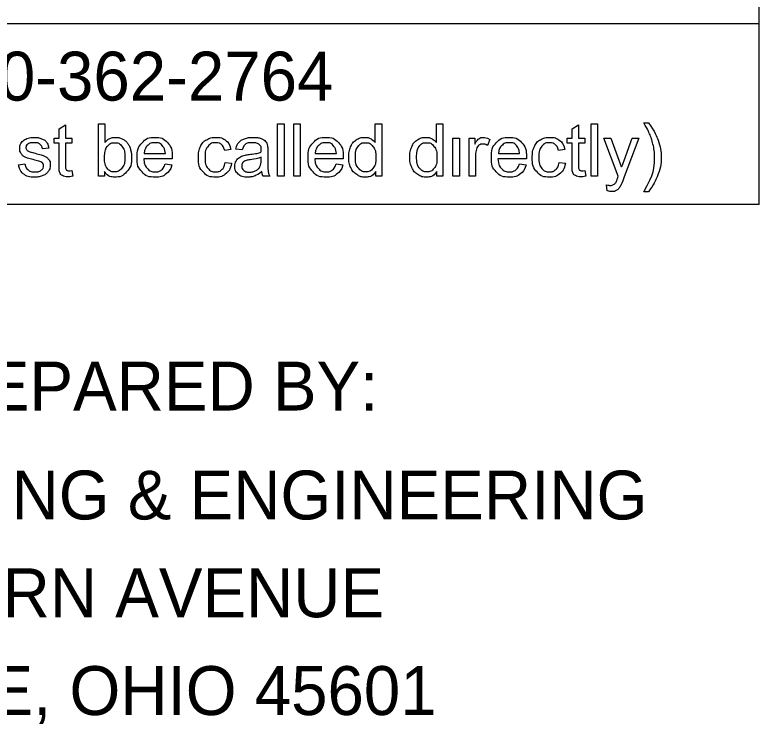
# Model space of a CAD drawing. Extents: x 0 to 82.7, y -0.2 to 22.
# Drawn here: x 55.657 to 57.787, y -0.049 to 1.983 of the extents above; entities that cross this region are included whole.
import ezdxf

# ---------------------------------------------------------------- set-up
doc = ezdxf.new("R2010")
doc.units = 0
doc.layers.add('SH_Data', color=7, linetype='Continuous')
doc.layers.add('SH_Text', color=7, linetype='Continuous')

msp = doc.modelspace()

# ---------------------------------------------------------------- linework, layer by layer
at = {"layer": 'SH_Data'}
for p, q in [((57.7873, 1.4393), (57.7873, 3.7768)), ((57.7873, 1.9571), (53.5373, 1.9571)), ((57.7873, 1.4393), (53.5373, 1.4393))]:
    msp.add_line(p, q, dxfattribs=at)
at = {"layer": 'SH_Text'}
for points in [[(55.783, 1.5522), (55.783, 1.6149), (55.7694, 1.6149), (55.7694, 1.6292), (55.783, 1.6292), (55.783, 1.6562), (55.8015, 1.6672), (55.8015, 1.6292), (55.8199, 1.6292), (55.8199, 1.6149), (55.8015, 1.6149), (55.8015, 1.5512)], [(55.9132, 1.5204), (55.8961, 1.5204), (55.8961, 1.6705), (55.9145, 1.6705), (55.9145, 1.617)], [(56.4088, 1.5204), (56.4088, 1.6705), (56.4272, 1.6705), (56.4272, 1.5204), (56.4088, 1.5204)], [(56.4554, 1.5204), (56.4554, 1.6705), (56.4738, 1.6705), (56.4738, 1.5204), (56.4554, 1.5204)], [(56.6883, 1.6167), (56.6883, 1.6705), (56.7067, 1.6705), (56.7067, 1.5204), (56.6897, 1.5204)], [(56.8632, 1.6167), (56.8632, 1.6705), (56.8816, 1.6705), (56.8816, 1.5204), (56.8645, 1.5204)], [(57.2518, 1.5522), (57.2518, 1.6149), (57.2382, 1.6149), (57.2382, 1.6292), (57.2518, 1.6292), (57.2518, 1.6562), (57.2702, 1.6672), (57.2702, 1.6292), (57.2887, 1.6292), (57.2887, 1.6149), (57.2702, 1.6149), (57.2702, 1.5512)], [(57.3063, 1.5204), (57.3063, 1.6705), (57.3247, 1.6705), (57.3247, 1.5204), (57.3063, 1.5204)], [(57.4571, 1.6731), (57.4703, 1.6731)], [(56.9106, 1.5204), (56.9106, 1.6292), (56.9291, 1.6292), (56.9291, 1.5204), (56.9106, 1.5204)], [(56.9569, 1.5204), (56.9569, 1.6292), (56.9735, 1.6292), (56.9735, 1.6127)], [(57.0159, 1.6257), (57.0095, 1.6087)], [(57.3841, 1.5203), (57.3428, 1.6292), (57.3627, 1.6292), (57.3853, 1.5664)], [(57.4008, 1.5658), (57.424, 1.6292), (57.4425, 1.6292), (57.4012, 1.5185)], [(55.7537, 1.6011), (55.7357, 1.5987)], [(56.3076, 1.5957), (56.2896, 1.5981)], [(56.0267, 1.5852), (56.0875, 1.5852)], [(56.2751, 1.5972), (56.2572, 1.5944)], [(56.3807, 1.5906), (56.3807, 1.566)], [(56.5163, 1.5852), (56.577, 1.5852)], [(56.9753, 1.5774), (56.9753, 1.5204), (56.9569, 1.5204)], [(57.0408, 1.5852), (57.1015, 1.5852)], [(57.231, 1.5972), (57.213, 1.5944)], [(55.6673, 1.5529), (55.6855, 1.5558)], [(56.1068, 1.5701), (56.0257, 1.5701)], [(56.0872, 1.5555), (56.1063, 1.5531)], [(56.2588, 1.5602), (56.2769, 1.5578)], [(56.362, 1.5682), (56.3621, 1.575)], [(56.5964, 1.5701), (56.5152, 1.5701)], [(56.5768, 1.5555), (56.5959, 1.5531)], [(57.1209, 1.5701), (57.0397, 1.5701)], [(57.1013, 1.5555), (57.1204, 1.5531)], [(57.2146, 1.5602), (57.2327, 1.5578)], [(55.8199, 1.5368), (55.8225, 1.5205)], [(56.6897, 1.5204), (56.6897, 1.5341)], [(56.8645, 1.5204), (56.8645, 1.5341)], [(57.2887, 1.5368), (57.2913, 1.5205)], [(55.9132, 1.534), (55.9132, 1.5204)], [(56.3865, 1.5204), (56.3673, 1.5204)], [(57.3525, 1.4786), (57.3505, 1.4959)], [(57.4703, 1.4762), (57.4571, 1.4762)]]:
    msp.add_lwpolyline(points, dxfattribs=at)
for points, degree in [([(57.4571, 1.4762), (57.4877, 1.5254), (57.4877, 1.5746), (57.4877, 1.5939), (57.4833, 1.6128), (57.4798, 1.6282), (57.4736, 1.6423), (57.4696, 1.6516), (57.4571, 1.6731)], 3), ([(57.4703, 1.6731), (57.4895, 1.6474), (57.4988, 1.6214), (57.5067, 1.5991), (57.5067, 1.5747), (57.5067, 1.5471), (57.4961, 1.5213), (57.4854, 1.4955), (57.4703, 1.4762)], 3), ([(55.6855, 1.5558), (55.6871, 1.5448), (55.6941, 1.5389), (55.7011, 1.5331), (55.7138, 1.5331), (55.7265, 1.5331), (55.7327, 1.5383), (55.7389, 1.5435), (55.7389, 1.5504), (55.7389, 1.5567), (55.7334, 1.5603), (55.7296, 1.5627), (55.7145, 1.5665), (55.6942, 1.5717), (55.6864, 1.5754), (55.6785, 1.5791), (55.6745, 1.5857), (55.6704, 1.5923), (55.6704, 1.6003), (55.6704, 1.6076), (55.6738, 1.6138), (55.6771, 1.62), (55.6828, 1.6241), (55.6871, 1.6272), (55.6946, 1.6294), (55.702, 1.6316), (55.7105, 1.6316), (55.7234, 1.6316), (55.7331, 1.6279), (55.7428, 1.6243), (55.7474, 1.6179), (55.752, 1.6116), (55.7537, 1.6011)], 3), ([(55.9145, 1.617), (55.9262, 1.6316), (55.9443, 1.6316), (55.9544, 1.6316), (55.9633, 1.6276), (55.9723, 1.6235), (55.9781, 1.6162), (55.9839, 1.6089), (55.9871, 1.5986), (55.9904, 1.5882), (55.9904, 1.5765), (55.9904, 1.5485), (55.9766, 1.5332), (55.9627, 1.518), (55.9434, 1.518), (55.9241, 1.518), (55.9132, 1.534)], 3), ([(56.1063, 1.5531), (56.1018, 1.5364), (56.0896, 1.5272), (56.0774, 1.518), (56.0585, 1.518), (56.0346, 1.518), (56.0206, 1.5327), (56.0067, 1.5474), (56.0067, 1.5739), (56.0067, 1.6013), (56.0208, 1.6165), (56.0349, 1.6316), (56.0574, 1.6316), (56.0793, 1.6316), (56.0931, 1.6168), (56.1069, 1.6019), (56.1069, 1.575), (56.1069, 1.5733), (56.1068, 1.5701)], 3), ([(56.2769, 1.5578), (56.2739, 1.5391), (56.2616, 1.5286), (56.2494, 1.518), (56.2316, 1.518), (56.2092, 1.518), (56.1957, 1.5326), (56.1821, 1.5472), (56.1821, 1.5744), (56.1821, 1.592), (56.1879, 1.6052), (56.1938, 1.6184), (56.2057, 1.625), (56.2177, 1.6316), (56.2317, 1.6316), (56.2494, 1.6316), (56.2607, 1.6227), (56.272, 1.6137), (56.2751, 1.5972)], 3), ([(56.2896, 1.5981), (56.292, 1.6097), (56.2976, 1.6168), (56.3033, 1.6239), (56.3139, 1.6278), (56.3246, 1.6316), (56.3386, 1.6316), (56.3525, 1.6316), (56.3612, 1.6284), (56.3699, 1.6251), (56.374, 1.6201), (56.3781, 1.6151), (56.3797, 1.6076), (56.3807, 1.6028), (56.3807, 1.5906)], 3), ([(56.5959, 1.5531), (56.5914, 1.5364), (56.5792, 1.5272), (56.567, 1.518), (56.5481, 1.518), (56.5242, 1.518), (56.5102, 1.5327), (56.4962, 1.5474), (56.4962, 1.5739), (56.4962, 1.6013), (56.5104, 1.6165), (56.5245, 1.6316), (56.547, 1.6316), (56.5689, 1.6316), (56.5827, 1.6168), (56.5965, 1.6019), (56.5965, 1.575), (56.5965, 1.5733), (56.5964, 1.5701)], 3), ([(56.6897, 1.5341), (56.6793, 1.518), (56.6592, 1.518), (56.6462, 1.518), (56.6353, 1.5252), (56.6244, 1.5323), (56.6184, 1.5452), (56.6124, 1.558), (56.6124, 1.5747), (56.6124, 1.591), (56.6178, 1.6042), (56.6232, 1.6175), (56.6341, 1.6246), (56.6449, 1.6316), (56.6583, 1.6316), (56.6681, 1.6316), (56.6758, 1.6275), (56.6835, 1.6234), (56.6883, 1.6167)], 3), ([(56.8645, 1.5341), (56.8542, 1.518), (56.8341, 1.518), (56.8211, 1.518), (56.8102, 1.5252), (56.7993, 1.5323), (56.7933, 1.5452), (56.7873, 1.558), (56.7873, 1.5747), (56.7873, 1.591), (56.7927, 1.6042), (56.7981, 1.6175), (56.809, 1.6246), (56.8198, 1.6316), (56.8332, 1.6316), (56.843, 1.6316), (56.8507, 1.6275), (56.8583, 1.6234), (56.8632, 1.6167)], 3), ([(56.9735, 1.6127), (56.9798, 1.6243), (56.9852, 1.628), (56.9906, 1.6316), (56.997, 1.6316), (57.0063, 1.6316), (57.0159, 1.6257)], 3), ([(57.1204, 1.5531), (57.1159, 1.5364), (57.1037, 1.5272), (57.0915, 1.518), (57.0726, 1.518), (57.0487, 1.518), (57.0347, 1.5327), (57.0207, 1.5474), (57.0207, 1.5739), (57.0207, 1.6013), (57.0349, 1.6165), (57.049, 1.6316), (57.0715, 1.6316), (57.0933, 1.6316), (57.1072, 1.6168), (57.121, 1.6019), (57.121, 1.575), (57.121, 1.5733), (57.1209, 1.5701)], 3), ([(57.2327, 1.5578), (57.2297, 1.5391), (57.2175, 1.5286), (57.2052, 1.518), (57.1874, 1.518), (57.1651, 1.518), (57.1515, 1.5326), (57.1379, 1.5472), (57.1379, 1.5744), (57.1379, 1.592), (57.1438, 1.6052), (57.1496, 1.6184), (57.1616, 1.625), (57.1735, 1.6316), (57.1875, 1.6316), (57.2053, 1.6316), (57.2165, 1.6227), (57.2278, 1.6137), (57.231, 1.5972)], 3), ([(55.7357, 1.5987), (55.7344, 1.6071), (55.7285, 1.6118), (55.7226, 1.6165), (55.7119, 1.6165), (55.6991, 1.6165), (55.6937, 1.6123), (55.6883, 1.6081), (55.6883, 1.6025), (55.6883, 1.5989), (55.6905, 1.596), (55.6928, 1.593), (55.6976, 1.5911), (55.7004, 1.5901), (55.7139, 1.5864), (55.7335, 1.5811), (55.7413, 1.5778), (55.749, 1.5745), (55.7534, 1.5681), (55.7579, 1.5618), (55.7579, 1.5524), (55.7579, 1.5432), (55.7525, 1.535), (55.7471, 1.5269), (55.7369, 1.5224), (55.7268, 1.518), (55.7139, 1.518), (55.6927, 1.518), (55.6815, 1.5268), (55.6704, 1.5356), (55.6673, 1.5529)], 3), ([(55.9129, 1.5756), (55.9129, 1.5561), (55.9182, 1.5473), (55.9269, 1.5331), (55.9418, 1.5331), (55.9538, 1.5331), (55.9626, 1.5436), (55.9714, 1.5541), (55.9714, 1.5749), (55.9714, 1.5962), (55.963, 1.6064), (55.9545, 1.6165), (55.9426, 1.6165), (55.9305, 1.6165), (55.9217, 1.606), (55.9129, 1.5955), (55.9129, 1.5756)], 3), ([(56.0875, 1.5852), (56.0862, 1.5989), (56.0805, 1.6058), (56.0717, 1.6165), (56.0576, 1.6165), (56.0449, 1.6165), (56.0363, 1.608), (56.0276, 1.5995), (56.0267, 1.5852)], 3), ([(56.2572, 1.5944), (56.2546, 1.6054), (56.2481, 1.611), (56.2416, 1.6165), (56.2324, 1.6165), (56.2185, 1.6165), (56.2098, 1.6065), (56.2011, 1.5965), (56.2011, 1.5749), (56.2011, 1.553), (56.2095, 1.543), (56.2179, 1.5331), (56.2314, 1.5331), (56.2423, 1.5331), (56.2496, 1.5398), (56.2568, 1.5464), (56.2588, 1.5602)], 3), ([(56.3636, 1.5338), (56.3533, 1.5251), (56.3438, 1.5216), (56.3344, 1.518), (56.3235, 1.518), (56.3056, 1.518), (56.296, 1.5267), (56.2864, 1.5355), (56.2864, 1.5491), (56.2864, 1.5571), (56.29, 1.5637), (56.2936, 1.5703), (56.2995, 1.5743), (56.3054, 1.5783), (56.3128, 1.5803), (56.3182, 1.5817), (56.3292, 1.5831), (56.3515, 1.5857), (56.362, 1.5894), (56.3621, 1.5932), (56.3621, 1.5942), (56.3621, 1.6055), (56.3569, 1.6102), (56.3499, 1.6164), (56.336, 1.6164), (56.323, 1.6164), (56.3168, 1.6119), (56.3106, 1.6073), (56.3076, 1.5957)], 3), ([(56.577, 1.5852), (56.5758, 1.5989), (56.5701, 1.6058), (56.5613, 1.6165), (56.5472, 1.6165), (56.5345, 1.6165), (56.5259, 1.608), (56.5172, 1.5995), (56.5163, 1.5852)], 3), ([(56.6314, 1.5747), (56.6314, 1.5538), (56.6402, 1.5434), (56.649, 1.5331), (56.661, 1.5331), (56.6731, 1.5331), (56.6815, 1.543), (56.69, 1.5529), (56.69, 1.5732), (56.69, 1.5955), (56.6814, 1.606), (56.6728, 1.6164), (56.6602, 1.6164), (56.6479, 1.6164), (56.6397, 1.6064), (56.6314, 1.5963), (56.6314, 1.5747)], 3), ([(56.8063, 1.5747), (56.8063, 1.5538), (56.8151, 1.5434), (56.8239, 1.5331), (56.8359, 1.5331), (56.848, 1.5331), (56.8564, 1.543), (56.8649, 1.5529), (56.8649, 1.5732), (56.8649, 1.5955), (56.8563, 1.606), (56.8477, 1.6164), (56.8351, 1.6164), (56.8228, 1.6164), (56.8145, 1.6064), (56.8063, 1.5963), (56.8063, 1.5747)], 3), ([(57.0095, 1.6087), (57.0028, 1.6126), (56.996, 1.6126), (56.99, 1.6126), (56.9852, 1.609), (56.9804, 1.6054), (56.9784, 1.5989), (56.9753, 1.5891), (56.9753, 1.5774)], 3), ([(57.1015, 1.5852), (57.1003, 1.5989), (57.0946, 1.6058), (57.0858, 1.6165), (57.0717, 1.6165), (57.059, 1.6165), (57.0504, 1.608), (57.0417, 1.5995), (57.0408, 1.5852)], 3), ([(57.213, 1.5944), (57.2104, 1.6054), (57.204, 1.611), (57.1975, 1.6165), (57.1882, 1.6165), (57.1743, 1.6165), (57.1656, 1.6065), (57.1569, 1.5965), (57.1569, 1.5749), (57.1569, 1.553), (57.1653, 1.543), (57.1737, 1.5331), (57.1873, 1.5331), (57.1981, 1.5331), (57.2054, 1.5398), (57.2127, 1.5464), (57.2146, 1.5602)], 3), ([(56.0257, 1.5701), (56.0267, 1.5521), (56.0358, 1.5426), (56.0449, 1.5331), (56.0586, 1.5331), (56.0687, 1.5331), (56.0759, 1.5384), (56.083, 1.5438), (56.0872, 1.5555)], 3), ([(56.3621, 1.575), (56.3521, 1.5709), (56.332, 1.568), (56.3206, 1.5664), (56.3159, 1.5643), (56.3112, 1.5623), (56.3086, 1.5584), (56.306, 1.5544), (56.306, 1.5496), (56.306, 1.5422), (56.3116, 1.5373), (56.3172, 1.5324), (56.3279, 1.5324), (56.3386, 1.5324), (56.3469, 1.5371), (56.3552, 1.5417), (56.3591, 1.5498), (56.362, 1.5561), (56.362, 1.5682)], 3), ([(56.3807, 1.566), (56.3807, 1.5403), (56.3818, 1.5335), (56.383, 1.5267), (56.3865, 1.5204)], 3), ([(56.5152, 1.5701), (56.5163, 1.5521), (56.5254, 1.5426), (56.5345, 1.5331), (56.5481, 1.5331), (56.5583, 1.5331), (56.5655, 1.5384), (56.5726, 1.5438), (56.5768, 1.5555)], 3), ([(57.0397, 1.5701), (57.0408, 1.5521), (57.0499, 1.5426), (57.059, 1.5331), (57.0726, 1.5331), (57.0828, 1.5331), (57.09, 1.5384), (57.0971, 1.5438), (57.1013, 1.5555)], 3), ([(57.3853, 1.5664), (57.3897, 1.5545), (57.3932, 1.5413), (57.3964, 1.5537), (57.4008, 1.5658)], 3), ([(55.8225, 1.5205), (55.8147, 1.5189), (55.8086, 1.5189), (55.7986, 1.5189), (55.7931, 1.5221), (55.7875, 1.5253), (55.7853, 1.5304), (55.783, 1.5356), (55.783, 1.5522)], 3), ([(55.8015, 1.5512), (55.8015, 1.5433), (55.8024, 1.541), (55.8034, 1.5387), (55.8056, 1.5374), (55.8078, 1.5361), (55.8118, 1.5361), (55.8149, 1.5361), (55.8199, 1.5368)], 3), ([(57.2913, 1.5205), (57.2835, 1.5189), (57.2774, 1.5189), (57.2674, 1.5189), (57.2618, 1.5221), (57.2563, 1.5253), (57.2541, 1.5304), (57.2518, 1.5356), (57.2518, 1.5522)], 3), ([(57.2702, 1.5512), (57.2702, 1.5433), (57.2712, 1.541), (57.2722, 1.5387), (57.2744, 1.5374), (57.2765, 1.5361), (57.2806, 1.5361), (57.2837, 1.5361), (57.2887, 1.5368)], 3), ([(56.3673, 1.5204), (56.3644, 1.5261), (56.3636, 1.5338)], 2), ([(57.3505, 1.4959), (57.3565, 1.4943), (57.361, 1.4943), (57.3671, 1.4943), (57.3708, 1.4964), (57.3745, 1.4984), (57.3768, 1.5021), (57.3786, 1.5048), (57.3825, 1.5158), (57.383, 1.5173), (57.3841, 1.5203)], 3), ([(57.4012, 1.5185), (57.3945, 1.5006), (57.3908, 1.4939), (57.3859, 1.4848), (57.3796, 1.4806), (57.3732, 1.4763), (57.3644, 1.4763), (57.3591, 1.4763), (57.3525, 1.4786)], 3)]:
    msp.add_open_spline(points, degree=degree, dxfattribs=at)

# ---------------------------------------------------------------- texts
for s, p in [('OHIO811, 8-1-1, or 1-800-362-2764', (53.5817, 1.7371)), ('PLAN PREPARED BY:', (54.7723, 0.8495)), ('DISTRICT 9 PLANNING & ENGINEERING', (53.8994, 0.5375)), ('650 EASTERN AVENUE', (54.6433, 0.2575)), ('CHILLICOTHE, OHIO 45601', (54.4709, -0.0225))]:
    msp.add_text(s, height=0.14, dxfattribs=at).set_placement(p)

doc.saveas('drawing.dxf')
